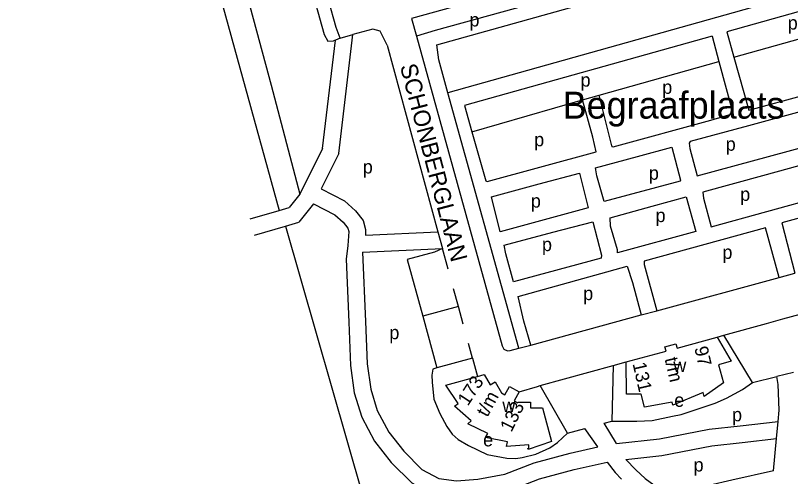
# Model space of a CAD drawing. Extents: x 159045 to 160918, y 380454 to 382516.
# Drawn here: x 159074.4 to 159304.8, y 380775.4 to 380912.4 of the extents above; entities that cross this region are included whole.
import ezdxf

# ---------------------------------------------------------------- set-up
doc = ezdxf.new("R2010")
doc.units = 0
for name, color, linetype in [('BLT_Basislijn', 7, 'Continuous'), ('BLT_Bebouwing', 7, 'Continuous'), ('BLT_Bebouwing_beschrifting', 7, 'Continuous'), ('BLT_Centroide', 7, 'Continuous'), ('BLT_Huisnummer_reeks', 7, 'Continuous'), ('BLT_Straatnaam', 7, 'Continuous'), ('BLT_Straatnaam_hoofdweg', 7, 'Continuous')]:
    doc.layers.add(name, color=color, linetype=linetype)

msp = doc.modelspace()

# ---------------------------------------------------------------- linework, layer by layer
at = {"layer": 'BLT_Basislijn'}
for p, q in [((159117.73, 381013.95), (159150.39, 380891.67)), ((159320.49, 380922.38), (159202.93, 380889.44)), ((159321.83, 380917.56), (159285.9, 380907.49)), ((159288.01, 380899.96), (159321.78, 380909.49)), ((159177.65, 380907.5), (159174.72, 380906.69)), ((159165.66, 380872.82), (159169.49, 380905.04)), ((159169.49, 380905.04), (159168.91, 380904.8)), ((159170.91, 380905.62), (159169.49, 380905.04)), ((159170.52, 380871.36), (159174.72, 380906.69)), ((159170.91, 380905.62), (159174.72, 380906.69)), ((159281.5, 380906.26), (159207.89, 380885.64)), ((159184.88, 380903.6), (159199.98, 380848.13)), ((159247.91, 380888.71), (159283.55, 380898.7)), ((159150.39, 380891.67), (159158.89, 380859.28)), ((159242.99, 380887.29), (159247.91, 380888.71)), ((159210.1, 380877.8), (159242.99, 380887.29)), ((159207.89, 380885.64), (159210.1, 380877.8)), ((159165.66, 380872.82), (159158.89, 380859.28)), ((159170.52, 380871.36), (159165.26, 380860.82)), ((159162.98, 380856.37), (159158.68, 380850.98)), ((159144.12, 380851.92), (159152.8, 380854.47)), ((159152.8, 380854.47), (159155.75, 380855.33)), ((159145.45, 380847.1), (159154.64, 380849.8)), ((159154.64, 380849.8), (159158.68, 380850.98)), ((159154.64, 380849.8), (159179.02, 380764.98)), ((159178.41, 380847.08), (159199.98, 380848.13)), ((159199.98, 380848.13), (159201.35, 380843.16)), ((159177.61, 380842.04), (159201.35, 380843.16)), ((159201.35, 380843.16), (159198.95, 380842.04)), ((159203.04, 380837), (159201.35, 380843.16)), ((159301.42, 380834.57), (159306.06, 380835.83)), ((159265.06, 380824.66), (159301.42, 380834.57)), ((159206.07, 380825.92), (159204.65, 380831.18)), ((159206.07, 380825.92), (159195.47, 380823.02)), ((159207.5, 380820.65), (159206.07, 380825.92)), ((159260.42, 380823.4), (159265.06, 380824.66)), ((159195.47, 380823.02), (159199.67, 380807.64)), ((159227.6, 380814.46), (159260.42, 380823.4)), ((159297.73, 380820.89), (159302.56, 380822.21)), ((159302.56, 380822.21), (159307.69, 380823.62)), ((159284.96, 380817.38), (159297.73, 380820.89)), ((159282.97, 380816.83), (159284.96, 380817.38)), ((159210.28, 380810.58), (159209.09, 380814.87)), ((159224.06, 380813.5), (159227.6, 380814.46)), ((159210.28, 380810.58), (159199.67, 380807.64)), ((159210.28, 380810.58), (159211.74, 380805.15)), ((159230.36, 380802.4), (159252.08, 380808.36)), ((159252.08, 380808.36), (159255.94, 380809.44)), ((159305.67, 380806.34), (159300.8, 380805.13)), ((159293.49, 380803.3), (159300.8, 380805.13)), ((159249.46, 380791.27), (159251.65, 380791.88)), ((159300.65, 380786.69), (159301.13, 380791.78)), ((159238.52, 380788.23), (159243.65, 380789.66)), ((159247.56, 380784.19), (159243.65, 380789.66)), ((159253.04, 380785.2), (159249.46, 380791.27)), ((159299.75, 380777.12), (159300.65, 380786.69))]:
    msp.add_line(p, q, dxfattribs=at)
for points in [[(159074.39, 381133.25), (159112.65, 381000), (159152.8, 380854.47)], [(159135.27, 381018.8), (159136.57, 381012.85), (159166.2, 380906.68), (159167.25, 380904.7), (159168.91, 380904.8)], [(159315.52, 380940.2), (159314.12, 380942.5), (159312.13, 380943.81), (159310.48, 380943.9), (159307.46, 380943.42), (159192.16, 380911.51), (159193.63, 380906.2)], [(159296.14, 380934.68), (159199.22, 380907.93), (159193.63, 380906.2)], [(159202.93, 380889.44), (159200.24, 380899.18), (159199.68, 380903.68), (159295.56, 380930.48), (159296.6, 380931.01), (159296.14, 380934.68)], [(159170.91, 380905.62), (159169.75, 380908.81), (159165.16, 380925.18)], [(159288.01, 380899.96), (159292.41, 380884.29), (159325.91, 380893.39), (159325.59, 380896.73), (159321.78, 380909.49)], [(159184.88, 380903.6), (159182.8, 380907.75), (159180.6, 380908.31), (159177.65, 380907.5)], [(159285.9, 380907.49), (159288.01, 380899.96)], [(159193.63, 380906.2), (159219.12, 380814.17), (159219.58, 380813.2), (159220.68, 380812.77), (159221.48, 380812.79), (159224.06, 380813.5)], [(159281.5, 380906.26), (159283.55, 380898.7)], [(159283.55, 380898.7), (159287.62, 380883.71), (159287.38, 380883.1), (159281.06, 380881.14), (159252.04, 380873.25), (159251.72, 380873.67), (159247.91, 380888.71)], [(159224.06, 380813.5), (159202.93, 380889.44)], [(159210.1, 380877.8), (159214.21, 380863.29), (159214.59, 380863.01), (159247.01, 380871.85), (159246.09, 380876.22), (159242.99, 380887.29)], [(159292.33, 380879.62), (159274.96, 380874.97), (159274.73, 380874.43), (159274.85, 380872.87), (159277.11, 380864.74), (159310, 380873.67), (159310.36, 380874.33), (159310.36, 380875.38), (159307.96, 380883.8), (159292.33, 380879.62)], [(159259.35, 380870.51), (159269.53, 380873.25), (159272.15, 380863.45), (159272.03, 380863.17), (159249.43, 380857.15), (159247.24, 380864.74), (159246.85, 380867.14), (159259.35, 380870.51)], [(159296.54, 380864.75), (159278.73, 380859.83), (159278.93, 380858.06), (159281.27, 380849.61), (159314.37, 380858.68), (159314.69, 380859.38), (159314.61, 380860.62), (159312.55, 380867.8), (159312.07, 380868.53), (159311.27, 380868.82), (159296.54, 380864.75)], [(159230.12, 380862.32), (159242.08, 380865.55), (159244.62, 380855.21), (159218.47, 380848.07), (159215.88, 380858.48), (159230.12, 380862.32)], [(159165.26, 380860.82), (159172.2, 380857.35), (159175.48, 380854.37), (159177.73, 380851.47), (159178.5, 380848.77), (159178.41, 380847.08)], [(159158.89, 380859.28), (159158.89, 380859.26), (159155.75, 380855.33)], [(159263.69, 380855.68), (159273.83, 380858.49), (159276.64, 380848.17), (159253.34, 380841.88), (159253.34, 380842.77), (159251.33, 380849.77), (159251.19, 380852.22), (159263.69, 380855.68)], [(159339.73, 380845), (159335.36, 380859.76), (159302.28, 380850.79), (159306.06, 380835.83)], [(159162.98, 380856.37), (159169.34, 380853.19), (159171.8, 380850.96), (159173.19, 380849.17), (159173.46, 380848.21), (159173.23, 380844.03), (159172.7, 380840), (159173.49, 380821.27), (159174.01, 380808.38), (159175.1, 380800.24), (159177.32, 380793.03), (159181.18, 380785.85), (159186.1, 380779.56), (159192.2, 380773.47), (159198.66, 380769.94), (159205.38, 380769.07), (159212.55, 380769.62), (159221.25, 380771.25), (159230.21, 380774.67), (159240.47, 380777.49), (159250.28, 380779.67)], [(159234.12, 380847.95), (159246.01, 380851.1), (159248.63, 380841.17), (159248.57, 380840.31), (159222.51, 380833.26), (159220.17, 380841.51), (159219.73, 380844.13), (159234.12, 380847.95)], [(159301.42, 380834.57), (159297.37, 380849.26), (159261.27, 380839.33), (159261.33, 380838.35), (159265.06, 380824.66)], [(159177.61, 380842.04), (159178.48, 380821.48), (159179, 380808.82), (159180, 380801.31), (159181.95, 380794.97), (159185.39, 380788.59), (159189.85, 380782.88), (159195.23, 380777.51), (159200.24, 380774.78), (159205.51, 380774.09), (159211.9, 380774.58), (159219.89, 380776.08), (159228.65, 380779.43), (159239.26, 380782.35), (159247.56, 380784.19)], [(159198.95, 380842.04), (159190.87, 380839.85), (159195.47, 380823.02)], [(159227.6, 380814.46), (159225.53, 380821.58), (159223.83, 380828.89), (159256.25, 380837.84), (159257.86, 380833.02), (159260.42, 380823.4)], [(159293.49, 380803.3), (159284.96, 380817.38)], [(159252.08, 380808.36), (159251.65, 380791.88)], [(159199.67, 380807.64), (159198.49, 380807.31), (159198.21, 380805.46), (159198.26, 380803.4), (159198.79, 380798.38), (159200.59, 380794.15), (159202.61, 380790.2), (159204.2, 380787.92), (159205.99, 380786.35), (159209.07, 380784.6), (159214.67, 380781.92), (159220.45, 380780.83), (159223.14, 380780.78), (159225.07, 380780.99), (159229.06, 380782.06), (159233.25, 380783.86), (159235.55, 380785.54), (159238.52, 380788.23)], [(159251.65, 380791.88), (159255.95, 380791.88), (159259.11, 380791.88), (159263.68, 380792.06), (159269.71, 380793.3), (159272.36, 380793.83), (159282.41, 380797.14), (159285.83, 380798.63), (159290.58, 380801.27), (159293.49, 380803.3)], [(159301.13, 380791.78), (159301.44, 380795.07), (159301.19, 380802.7), (159300.8, 380805.13)], [(159224.14, 380800.5), (159229.56, 380802.18), (159230.36, 380802.4)], [(159238.52, 380788.23), (159230.36, 380802.4)], [(159253.04, 380785.2), (159265.83, 380786.57), (159280.68, 380789.43), (159289.9, 380790.49), (159301.13, 380791.78)], [(159255.83, 380780.47), (159266.57, 380781.62), (159281.44, 380784.49), (159290.47, 380785.52), (159300.65, 380786.69)], [(159255.83, 380780.47), (159258.88, 380777.41), (159261.61, 380774.81), (159265.27, 380772.13), (159266.83, 380769.57)], [(159250.28, 380779.67), (159252.64, 380776.58), (159254.6, 380774.62)], [(159299.75, 380777.12), (159287.38, 380774.25), (159266.83, 380769.57)]]:
    msp.add_lwpolyline(points, dxfattribs=at)
at = {"layer": 'BLT_Bebouwing'}
for points in [[(159282.97, 380816.83), (159287.18, 380809.64), (159283.4, 380808.56), (159284.85, 380803.2), (159279.18, 380799.16), (159278.87, 380800.36), (159269.86, 380796.57), (159269.67, 380797.5), (159261.43, 380796), (159260.4, 380799.84), (159256.06, 380799.82), (159255.94, 380809.44)], [(159255.94, 380809.44), (159267.83, 380812.67), (159267.48, 380813.92), (159270.77, 380814.82), (159271.1, 380813.56), (159282.97, 380816.83)], [(159211.74, 380805.15), (159213.73, 380805.69), (159215.53, 380802.63), (159216.97, 380803.47), (159218.89, 380800.24), (159219.84, 380799.66), (159221.27, 380802.13), (159224.14, 380800.5)], [(159204.89, 380796.33), (159206.01, 380797.07), (159202.34, 380802.57), (159211.74, 380805.15)], [(159224.14, 380800.5), (159222.68, 380797.86), (159223.7, 380797.32), (159223.73, 380797.46), (159227.48, 380797.49), (159227.5, 380795.8), (159231.04, 380795.81), (159233.78, 380785.79), (159226.84, 380783.39), (159226.75, 380783.69), (159226.98, 380783.8), (159226.99, 380784.82), (159220.36, 380784.34)], [(159208.92, 380791.03), (159209.89, 380791.97), (159204.89, 380796.33)], [(159214.18, 380786.93), (159214.86, 380788.12), (159208.92, 380791.03)], [(159220.36, 380784.34), (159220.68, 380785.65), (159214.18, 380786.93)]]:
    msp.add_lwpolyline(points, dxfattribs=at)

# ---------------------------------------------------------------- texts
at = {"layer": 'BLT_Bebouwing_beschrifting'}
msp.add_text('Begraafplaats', height=8, dxfattribs=at).set_placement((159237.06, 380881.73))
at = {"layer": 'BLT_Centroide'}
for s, p in [('p', (159209.36, 380909.12)), ('p', (159303.99, 380908.19)), ('p', (159242.4, 380891.23)), ('p', (159266.69, 380889.08)), ('p', (159228.61, 380873.51)), ('p', (159285.56, 380872.19)), ('p', (159177.65, 380865.42)), ('p', (159262.71, 380863.57)), ('p', (159227.62, 380855.29)), ('p', (159289.86, 380857.28)), ('p', (159264.7, 380850.99)), ('p', (159230.93, 380842.37)), ('p', (159284.57, 380840.05)), ('p', (159243.18, 380827.8)), ('p', (159185.55, 380816.17)), ('w', (159269.98, 380806.41)), ('e', (159270.27, 380796.1)), ('w', (159219.16, 380794.53)), ('p', (159287.44, 380791.79)), ('e', (159213.42, 380784.34)), ('p', (159276.01, 380776.86))]:
    msp.add_text(s, height=4, dxfattribs=at).set_placement(p)
at = {"layer": 'BLT_Huisnummer_reeks'}
for s, rotation, p in [('97', 282.9341, (159276.21, 380813.61)), ('t/m', 282.9341, (159267.38, 380810.37)), ('131', 282.9341, (159257.84, 380808.91)), ('173', 56.9341, (159208.9, 380796.15)), ('t/m', 61.488, (159214.68, 380792.8)), ('133', 63.5377, (159221.83, 380788.37))]:
    msp.add_text(s, height=4, rotation=rotation, dxfattribs=at).set_placement(p)
at = {"layer": 'BLT_Straatnaam'}
msp.add_text('SCHONBERGLAAN', height=5, rotation=284.692, dxfattribs=at).set_placement((159188.66, 380897.36))
at = {"layer": 'BLT_Straatnaam_hoofdweg'}
msp.add_text('LOCATELLISTRAAT', height=8, rotation=12.0735, dxfattribs=at).set_placement((159245.82, 380750.55))

doc.saveas('drawing.dxf')
